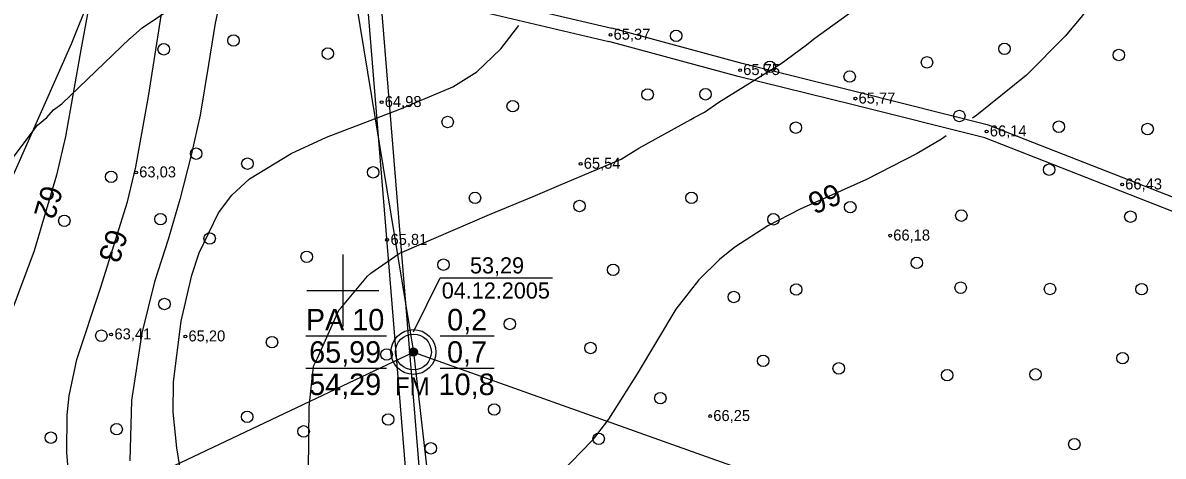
# Model space of a CAD drawing. Extents: x 532503 to 539665, y 6557663 to 6561526.
# Drawn here: x 534128.7 to 534382.9, y 6559763.1 to 6559859.6 of the extents above; entities that cross this region are included whole.
import ezdxf

# ---------------------------------------------------------------- set-up
doc = ezdxf.new("R2010")
doc.units = 0
for name, color, linetype in [('GEOLPUNKT', 7, 'Continuous'), ('HALJASTUS', 7, 'Continuous'), ('HORISONTAAL-EH2000', 7, 'Continuous'), ('KORGUS-EH2000', 7, 'Continuous'), ('Lamami horisontaal_EH2000', 7, 'Continuous'), ('Lõige', 7, 'Continuous'), ('Proovid', 7, 'Continuous'), ('TEE', 7, 'Continuous'), ('Veetase', 7, 'Continuous'), ('VORK', 7, 'Continuous')]:
    doc.layers.add(name, color=color, linetype=linetype)

# ---------------------------------------------------------------- blocks, each defined once
blk = doc.blocks.new('METS')
at = {"layer": 'HALJASTUS'}
blk.add_circle((0, 0), 0.8, dxfattribs=at)

msp = doc.modelspace()

# ---------------------------------------------------------------- linework, layer by layer
at = {"layer": 'GEOLPUNKT'}
for p, q in [((534191.74, 6559789.91), (534209.74, 6559789.91)), ((534221.74, 6559789.91), (534233.74, 6559789.91)), ((534191.74, 6559782.71), (534209.74, 6559782.71)), ((534221.74, 6559782.71), (534233.74, 6559782.71))]:
    msp.add_line(p, q, dxfattribs=at)
for radius in [5, 4, 0.9, 0.801, 0.7, 0.6, 0.5, 0.4, 0.3, 0.2, 0.1]:
    msp.add_circle((534215.74, 6559786.31), radius, dxfattribs=at)
at = {"layer": 'HALJASTUS'}
msp.add_lwpolyline([(534020.23, 6559948.58), (534037.72, 6559925.98), (534054.08, 6559915.24), (534069.41, 6559912.68), (534077.59, 6559900.41), (534080.66, 6559886.09), (534091.4, 6559877.39), (534112.36, 6559885.07), (534129.23, 6559891.2), (534145.08, 6559887.11), (534147.64, 6559875.35), (534139.46, 6559854.89), (534110.31, 6559789.42), (534101.11, 6559757.71), (534086.8, 6559745.95), (534070.44, 6559724.98), (534054.08, 6559721.91), (534040.79, 6559718.84), (534030.56, 6559697.87), (534027.49, 6559680.99), (534017.27, 6559666.67), (534010.62, 6559633.93), (534011.64, 6559613.48)], dxfattribs=at)
at = {"layer": 'HORISONTAAL-EH2000'}
for points in [[(534182.43, 6559975.49), (534172.44, 6559964.53), (534169.77, 6559960.94), (534165.41, 6559953.1), (534162.77, 6559946.69), (534158.72, 6559933.41), (534150.52, 6559898.08), (534144.99, 6559871.77), (534141.6, 6559853.64), (534138.19, 6559834.34), (534136.21, 6559825.74), (534131.22, 6559808.83), (534126.06, 6559795.09)], [(534139.12, 6559756.96), (534138.5, 6559763.84), (534138.55, 6559772.33), (534138.99, 6559776.54), (534140.7, 6559784.67), (534145.97, 6559800.53), (534152.02, 6559819.79), (534153.85, 6559827.53), (534156.71, 6559843.2), (534160.62, 6559868.3), (534166.83, 6559896.51), (534172.94, 6559919.42), (534180.67, 6559941), (534184.58, 6559949.52), (534187.02, 6559953.46), (534190.29, 6559957.45), (534196.28, 6559962.81)], [(534443.39, 6559949.02), (534436.51, 6559946.74), (534429.24, 6559945.53), (534419.96, 6559943.88), (534415.73, 6559942.3), (534409.93, 6559938.22), (534406.53, 6559934.63), (534400.62, 6559926.35), (534396.08, 6559918.65), (534388.2, 6559903.1), (534378.92, 6559883.92), (534373.8, 6559874.53), (534364.89, 6559861.31), (534360.98, 6559856.64), (534352.36, 6559847.99), (534341.3, 6559839.05), (534340.37, 6559838.42)], [(534202.11, 6559890.1), (534190.75, 6559884.84), (534184, 6559881.37), (534179.28, 6559877.96), (534177.24, 6559875.93), (534174.88, 6559872.43), (534173.01, 6559866.49), (534171.52, 6559859.58), (534170.06, 6559850.36), (534168.2, 6559839.11), (534166.24, 6559830.18), (534163.71, 6559820.26), (534161.06, 6559811.41), (534158.04, 6559801.93), (534155.21, 6559790.54), (534152.89, 6559775.47), (534152.55, 6559762.1)], [(534165.55, 6559749.27), (534163, 6559764.99), (534162.23, 6559772.87), (534162.26, 6559779.66), (534163.94, 6559793.18), (534166.35, 6559803.42), (534168.02, 6559808.43), (534172.32, 6559817.33), (534175.26, 6559821.23), (534179.19, 6559824.86), (534188.48, 6559830.53), (534196.4, 6559834.17), (534212.68, 6559840.39), (534224.56, 6559845.4), (534229.86, 6559848.76), (534235.22, 6559853.83), (534239.24, 6559859.06)], [(534334.46, 6559834.45), (534333.43, 6559833.76), (534327.99, 6559830.52), (534316.75, 6559824.73), (534301.94, 6559818.11), (534294.71, 6559814.41), (534287.4, 6559809.66), (534283.99, 6559806.94), (534279.33, 6559802.42), (534274.21, 6559795.86), (534265.58, 6559781.47), (534259.24, 6559771.37), (534255.61, 6559766.59), (534248.5, 6559759.31), (534244.47, 6559756.27), (534237.87, 6559752.83), (534224.2, 6559749.26), (534218.79, 6559747.12)]]:
    msp.add_lwpolyline(points, dxfattribs=at)
at = {"layer": 'KORGUS-EH2000'}
for centre in [(534259.66, 6559856.98), (534288.56, 6559849.11), (534314.25, 6559842.76), (534208.66, 6559841.98), (534343.51, 6559835.44), (534253, 6559828.24), (534153.93, 6559826.31), (534373.7, 6559823.62), (534322, 6559812.24), (534209.86, 6559811.27), (534148.34, 6559790.22), (534164.91, 6559789.77), (534281.89, 6559772.03)]:
    msp.add_circle(centre, 0.32, dxfattribs=at)
at = {"layer": 'Lamami horisontaal_EH2000'}
for points in [[(534118.69, 6559819.25), (534131.96, 6559836.85), (534134.06, 6559838.59), (534135.53, 6559840.28), (534137.35, 6559841.62), (534152.54, 6559856.14), (534152.66, 6559856.21), (534155.29, 6559858.51), (534176.9, 6559873.07)], [(534192.32, 6559752.6), (534192.51, 6559774.1), (534193.5, 6559783.14), (534194.37, 6559784.92), (534199.11, 6559795.6), (534199.53, 6559796.07), (534205.51, 6559803.24), (534206.25, 6559803.89), (534212.53, 6559808.22), (534212.72, 6559808.36), (534232.7, 6559816.98), (534242.45, 6559820.97), (534248.16, 6559823.39), (534262.05, 6559829.26), (534265.97, 6559831.7), (534277.6, 6559838.09), (534278.35, 6559838.59), (534280.61, 6559839.77), (534283.79, 6559842), (534297.68, 6559850.58), (534303.09, 6559854.55), (534305.24, 6559856.21), (534313.72, 6559862.38)]]:
    msp.add_lwpolyline(points, dxfattribs=at)
at = {"layer": 'Lõige'}
for points in [[(534196.94, 6560008.33), (534199.17, 6559979.56), (534201.3, 6559874.5), (534215.74, 6559786.31), (534234.02, 6559626.35), (534236.27, 6559544.42), (534237.9, 6559498.78), (534199.31, 6559446.85), (534164.07, 6559400.22), (534154.58, 6559387.66)], [(533917.43, 6559650.43), (533949.04, 6559659.85), (534215.74, 6559786.31), (534470.46, 6559695.5), (534707.91, 6559763.06), (534929.16, 6559826.01), (535198.18, 6559814.49), (535305.66, 6559887.85), (535520.8, 6559960.87), (535543.92, 6559971)]]:
    msp.add_lwpolyline(points, dxfattribs=at)
at = {"layer": 'TEE'}
for p, q in [((534214.08, 6559759.73), (534205.15, 6559869.25)), ((534208.04, 6559870.64), (534259.99, 6559858.44)), ((534217.07, 6559760.02), (534208.3, 6559867.51)), ((534208.3, 6559867.51), (534259.33, 6559855.51)), ((534289, 6559850.55), (534259.99, 6559858.44)), ((534288.11, 6559847.68), (534259.33, 6559855.51)), ((534314.74, 6559844.18), (534289, 6559850.55)), ((534313.76, 6559841.34), (534288.11, 6559847.68)), ((534343.92, 6559836.88), (534314.74, 6559844.18)), ((534343.11, 6559834), (534313.76, 6559841.34)), ((534404.24, 6559813.24), (534343.92, 6559836.88)), ((534402.87, 6559810.57), (534343.11, 6559834))]:
    msp.add_line(p, q, dxfattribs=at)
at = {"layer": 'Veetase'}
for p, q in [((534215.74, 6559790.81), (534221.74, 6559802.81)), ((534221.74, 6559802.81), (534246.74, 6559802.81))]:
    msp.add_line(p, q, dxfattribs=at)
at = {"layer": 'VORK'}
for p, q in [((534200, 6559808), (534200, 6559792)), ((534192, 6559800), (534208, 6559800))]:
    msp.add_line(p, q, dxfattribs=at)

# ---------------------------------------------------------------- block references
at = {"layer": 'HALJASTUS', "xscale": 1.6, "yscale": 1.6000000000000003}
for p in [(534175.64, 6559855.7), (534274.3, 6559856.75), (534160.09, 6559853.75), (534196.67, 6559852.79), (534347.49, 6559853.87), (534372.97, 6559852.48), (534295.19, 6559849.83), (534330.21, 6559850.85), (534312.97, 6559847.67), (534267.94, 6559843.69), (534280.83, 6559843.73), (534237.88, 6559841.09), (534223.37, 6559837.56), (534337.42, 6559838.89), (534300.96, 6559836.29), (534359.59, 6559836.5), (534379.38, 6559835.98), (534167.33, 6559830.49), (534178.74, 6559828.26), (534357.45, 6559826.93), (534148.37, 6559825.35), (534206.77, 6559826.33), (534229.47, 6559820.64), (534277.72, 6559820.67), (534252.76, 6559818.84), (534313.11, 6559818.58), (534337.87, 6559816.7), (534375.55, 6559816.46), (534137.94, 6559815.52), (534159.36, 6559815.91), (534295.98, 6559815.88), (534170.33, 6559811.59), (534191.96, 6559807.53), (534327.93, 6559806.16), (534222.45, 6559805.76), (534260.25, 6559804.62), (534287.14, 6559798.57), (534301.07, 6559800.22), (534337.72, 6559800.63), (534357.62, 6559800.34), (534378.05, 6559800.31), (534160.24, 6559797), (534237.24, 6559792.54), (534146.19, 6559789.94), (534184.22, 6559788.5), (534255.23, 6559787.21), (534209.77, 6559785.74), (534293.69, 6559784.33), (534373.81, 6559784.95), (534310.54, 6559782.66), (534334.7, 6559781.14), (534354.4, 6559781.32), (534270.78, 6559776.02), (534233.73, 6559773.5), (534178.68, 6559771.88), (534210.12, 6559771.27), (534149.59, 6559769.1), (534191.27, 6559768.62), (534134.93, 6559767.22), (534257.04, 6559766.95), (534363.05, 6559765.78), (534219.61, 6559764.84)]:
    msp.add_blockref('METS', p, dxfattribs=at)

# ---------------------------------------------------------------- texts
at = {"layer": 'GEOLPUNKT'}
for s, p in [('PA 10', (534191.77, 6559791.11)), ('0,2', (534223.26, 6559791.11)), ('65,99', (534192.5, 6559783.91)), ('0,7', (534223.23, 6559783.91)), ('54,29', (534192.5, 6559776.71)), ('10,8', (534221.36, 6559776.71))]:
    msp.add_text(s, height=4.8, dxfattribs=at).set_placement(p)
at = {"layer": 'HORISONTAAL-EH2000'}
for s, rotation, p in [('62', 253.603, (534133.12, 6559823.79)), ('66', 202.5107, (534309.83, 6559824.05)), ('63', 252.3499, (534147.67, 6559814.05))]:
    msp.add_text(s, height=4.8, rotation=rotation, dxfattribs=at).set_placement(p)
at = {"layer": 'KORGUS-EH2000'}
for s, p in [('65,37', (534260.35, 6559855.88)), ('65,75', (534289.25, 6559848.01)), ('64,98', (534209.35, 6559840.88)), ('65,77', (534314.95, 6559841.66)), ('66,14', (534344.21, 6559834.34)), ('65,54', (534253.7, 6559827.14)), ('63,03', (534154.62, 6559825.21)), ('66,43', (534374.39, 6559822.52)), ('65,81', (534210.63, 6559810.17)), ('66,18', (534322.69, 6559811.14)), ('63,41', (534149.11, 6559789.12)), ('65,20', (534165.6, 6559788.67)), ('66,25', (534282.58, 6559770.93))]:
    msp.add_text(s, height=2.45, dxfattribs=at).set_placement(p)
at = {"layer": 'Proovid'}
msp.add_text('FM', height=4, dxfattribs=at).set_placement((534211.62, 6559776.67))
at = {"layer": 'Veetase'}
for s, p in [('53,29', (534228.36, 6559803.81)), ('04.12.2005', (534222.06, 6559798.21))]:
    msp.add_text(s, height=3.6, dxfattribs=at).set_placement(p)

doc.saveas('drawing.dxf')
